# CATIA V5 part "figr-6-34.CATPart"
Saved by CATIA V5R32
Part number: Part1
Bounding box of the stored display mesh (mm): x -61 to 61, y 0 to 173.636, z 0 to 130.49
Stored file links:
  D:\PROJECTS\Project 2022\CATIA V5 6R 2022\Resources\Part Files\c06_catia_v5_6r2022_prt\figr-6-34.CATPart
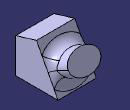
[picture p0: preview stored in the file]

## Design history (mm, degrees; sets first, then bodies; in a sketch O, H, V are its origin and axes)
Body1 (main body)
  Sketch1 on yz-plane, origin (0, 0, 0), H (0, 1, 0), V (0, 0, 1)
    line L1 (0, 0) -> (0, 110.5903)
    line L2 (0, 110.5903) -> (66.2814, 130.4899)
    line L3 (66.2814, 130.4899) -> (135.1646, 0)
    point P3 (135.1646, 0)
    line L4 (135.1646, 0) -> (0, 0)
    vertical: L1 V
    coincidence: P3 H
    horizontal: L4 H
  Pad1: profile Sketch1, direction (1, 0, 0), length 61, mirrored extent
  Sketch2 on face of Pad1, origin (0, 105.7081, 55.8014), H (-1, 0, 0), V (0, -0.4668, 0.8843)
    point P1 (0, 4.9672)
    ellipse A1 centre (0, 4.9672) semi-axes 50.9663, 34.9201 rotation 0
    coincidence: P1 V
  Pad2: profile Sketch2, direction (0, 0.8843, 0.4668), length 61
  Fillet1: radius 29, on edge [face of Pad1 | face of Pad2]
